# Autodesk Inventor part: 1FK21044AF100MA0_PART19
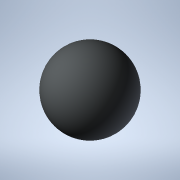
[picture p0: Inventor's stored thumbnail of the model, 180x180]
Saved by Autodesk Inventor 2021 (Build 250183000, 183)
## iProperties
Created: 2025-04
Part Number: 1FK21044AF100MA0_PART19
Material: Generic
Catalog Web Link: www.3dfindit.com
Description: -Servo synchronous motor
Document SubType Name: Modeling
Designer: psAdmin
Mass: 0.137258 g
Surface Area: 1.2868 cm^2
Volume: 0.137258 cm^3
Density: 1 g/cm^3
Appearance: PSOLRGB-212-217-219
Category: PARTsolutions
Title: 1FK21044AF100MA0_PART19
Author: Cadenas PARTsolutions
Comments: Servo synchronous motor
Sending System: PARTsolutions
Preprocessor: ST-DEVELOPER v19.3
PSOL_IDENT_0: {$CADENAS_DATA/23d-libs/siemens_ag/_cat_/ec/e4/1fk21044af100ma0.prj},216 {VTYP=3D},{NB=1FK21044AF100
PSOL_IDENT_1: MA0_PART19},{LINA=1FK21044AF100MA0_PART19},{NN=1FK21044AF100MA0_PART19},{NOPRJ=TRUE},{DATE=19.08.202
PSOL_IDENT_2: 5 14:01:05},{GEOMDATE=30.07.2025 02:01:01},{VERSION=},{LINEID=10},{WBVAR=},{WBNUMERIC=}  {NB=1FK2104
PSOL_IDENT_3: 4AF100MA0_PART19},{LINA=1FK21044AF100MA0_PART19},{KT=DUMMY},{PREVIEW=../../../_pool_/cb/72/p_d211_xx
PSOL_IDENT_4: _00434j.png},{DESCSHORT=SIMOTICS S-1FK2 HD, SINAMICS S210 3AC 400V-480V, 1.27 Nm, 3000 rpm},{DESCLON
PSOL_IDENT_5: G=SIMOTICS S-1FK2 HD servo motor M0=1.27 Nm; PN = 0.4 kW at nN=3000 rpm (380-480 V); PN = 0.2 kW at
PSOL_IDENT_6: nN=1500 rpm (200-240 V); with holding brake; degree of protection IP64; cylindrical shaft D19x40mm;
PSOL_IDENT_7: absolute encoder 22-bit + 12-bit multiturn (encoder AM22DQC); with OCC interface; plug size M17, rot
PSOL_IDENT_8: atable; SIMOTICS S-1FK2 servomotorfor a wide range of uses in industrial environments. SIMOTICS S‑1F
PSOL_IDENT_9: K2 servomotors are compact synchronous motors with a high dynamic performance that set themselves ap
PSOL_IDENT_10: art as a result of their high power density, degree of protection and overload capability. The motor
PSOL_IDENT_11: s are available in two variants: as High Dynamic variant (highest dynamic performance as a result of
PSOL_IDENT_12: the low intrinsic moment of inertia for applications demanding a high dynamic performance with low
PSOL_IDENT_13: moved masses) - and as Compact variant (precise and stable closed-loop control for medium up to larg
PSOL_IDENT_14: e moved masses as a result of a medium intrinsic moment of inertia). SIMOTICSS‑1FK2 servomotors full
PSOL_IDENT_15: y exploit their strengths in a system with the SINAMICSS210 frequency converter and simple connectio
PSOL_IDENT_16: n using the one cable connection (OCC). Advantages include the short control and positioning times,
PSOL_IDENT_17: fast and precise correction of disturbing quantities as well as stable control with a high dynamic p
PSOL_IDENT_18: erformance. The servo motors can be configured to address a wide range of requirements. For example
PSOL_IDENT_19: with and without holding brake, IP64 or IP65 degree of protection, singleturn or multiturn absolute
PSOL_IDENT_20: encoders - to name just a few. Further, the servomotors are available in different shaft heights ext
PSOL_IDENT_21: ending from 20 to 100. A shaft sealing ring is available to achieve an IP65 degree of protection and
PSOL_IDENT_22: for subsequent mounting at the motor or as spare part. SIMOTICS - the optimum motor for each and ev
PSOL_IDENT_23: ery motion control application.},{INTNO=195125043275},{SUPPLIERALTNO=1FK2104-4AF10-0MA0},{MANUID=1FK
PSOL_IDENT_24: 21044AF100MA0},{MANUNAME=Siemens},{MANUTYPEDESC=Synchronous motor 1FK2-HD 1.27 NM},{AAU732=SIMOTICS}
PSOL_IDENT_25: ,{AAO057=S-1FK2},{AAU734=SIMOTICS S-1FK2 HD servo motor M0=1.27 Nm; PN = 0.4 kW at nN=3000 rpm (380-
PSOL_IDENT_26: 480 V); PN = 0.2 kW at nN=1500 rpm (200-240 V); with holding brake; degree of protection IP64; cylin
PSOL_IDENT_27: drical shaft D19x40mm; absolute encoder 22-bit + 12-bit multiturn (encoder AM22DQC); with OCC interf
PSOL_IDENT_28: ace; plug size M17, rotatable;},{AAW338=Synchronous motor 1FK2-HD 1.27 NM},{AAO742=SIMOTICS},{AAO663=
PSOL_IDENT_29: 4042948694015},{NOCUPEROU=1},{PRICEQUANTITY=1},{QUANTITYMIN=1},{QUANTITYINT=1},{CTN=85015100},{COO=D
PSOL_IDENT_30: E},{AAO676=1FK2104-4AF10-0MA0},{AAO677=Siemens AG},{ORDERUNIT=C62},{CONTENTUNIT=C62}
NB: 1FK21044AF100MA0_PART19
NT: Servo synchronous motor
NBSYN: $MANUID._PART19
LINA: 1FK21044AF100MA0_PART19
CATALOG: SIEMENS
PREVIEW: ../../../_pool_/cb/72/p_d211_xx_00434j.png
DESCSHORT: SIMOTICS S-1FK2 HD, SINAMICS S210 3AC 400V-480V, 1.27 Nm, 3000 rpm
DESCLONG: SIMOTICS S-1FK2 HD servo motor M0=1.27 Nm; PN = 0.4 kW at nN=3000 rpm (380-480 V); PN = 0.2 kW at nN=1500 rpm (200-240 V); with holding brake; degree of protect
INTNO: 195125043275
SUPPLIERALTNO: 1FK2104-4AF10-0MA0
MANUID: 1FK21044AF100MA0
MANUNAME: Siemens
MANUTYPEDESC: Synchronous motor 1FK2-HD 1.27 NM
AAU732: SIMOTICS
AAO057: S-1FK2
AAU734: SIMOTICS S-1FK2 HD servo motor M0=1.27 Nm; PN = 0.4 kW at nN=3000 rpm (380-480 V); PN = 0.2 kW at nN=1500 rpm (200-240 V); with holding brake; degree of protect
AAW338: Synchronous motor 1FK2-HD 1.27 NM
AAO742: SIMOTICS
AAO663: 4042948694015.0
NOCUPEROU: 1
PRICEQUANTITY: 1
QUANTITYMIN: 1
QUANTITYINT: 1
CTN: 85015100
COO: DE
ARTICLENO: 1FK21044AF100MA0_PART19
BOMINFO: 1FK21044AF100MA0_PART19
CREATOR: CADENAS GmbH
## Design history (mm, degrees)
feature "2025_04_17_15_33_01_0673"
body "Solid1"
